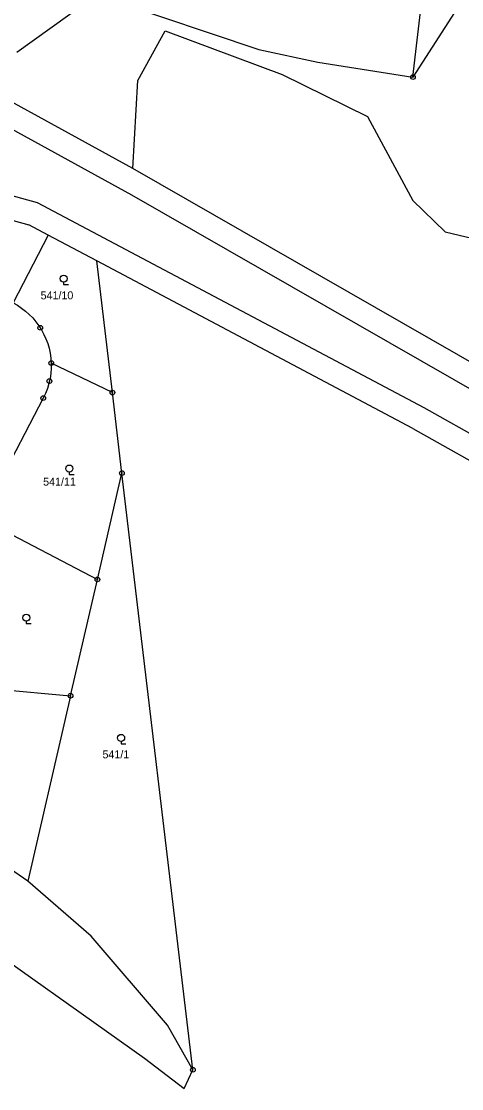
# Model space of a CAD drawing. Extents: x -759947 to -757003, y -1019641 to -1017100.
# Drawn here: x -757914.5 to -757821, y -1019278.9 to -1019052.2 of the extents above; entities that cross this region are included whole.
import ezdxf

# ---------------------------------------------------------------- set-up
doc = ezdxf.new("R2010")
doc.units = 0
doc.header["$LTSCALE"] = 0.68
for name, color, linetype, lineweight in [('1', 7, 'Continuous', 25), ('3', 7, 'Continuous', 25), ('8', 7, 'Continuous', 25)]:
    doc.layers.add(name, color=color, linetype=linetype, lineweight=lineweight)
doc.layers.add('2', color=7, linetype='Continuous')

msp = doc.modelspace()

# ---------------------------------------------------------------- linework, layer by layer
at = {"layer": '1'}
for p, q in [((-757831.29, -1019064.07), (-757827.47, -1019030.73)), ((-757813.04, -1019035.6), (-757831.29, -1019064.07)), ((-757895.26, -1019047.74), (-757864.04, -1019058.25)), ((-757963.05, -1019049.56), (-757891.09, -1019089.05)), ((-757915.46, -1019058.79), (-757900.92, -1019048.35)), ((-757890.77, -1019083.52), (-757947.21, -1019052.53)), ((-757889.7, -1019064.83), (-757883.96, -1019054.22)), ((-757883.96, -1019054.22), (-757859.04, -1019063.51)), ((-757864.04, -1019058.25), (-757851.51, -1019060.88)), ((-757851.51, -1019060.88), (-757831.29, -1019064.07)), ((-757859.04, -1019063.51), (-757840.93, -1019072.43)), ((-757890.77, -1019083.52), (-757889.7, -1019064.83)), ((-757840.93, -1019072.43), (-757831.31, -1019090.29)), ((-757810.34, -1019129.59), (-757890.77, -1019083.52)), ((-757911.01, -1019090.78), (-757918.97, -1019088.6)), ((-757828.94, -1019134.35), (-757911.01, -1019090.78)), ((-757891.09, -1019089.05), (-757812.79, -1019133.95)), ((-757831.31, -1019090.29), (-757824.44, -1019096.92)), ((-757920.78, -1019093.29), (-757912.86, -1019095.46)), ((-757908.76, -1019097.64), (-757912.86, -1019095.46)), ((-757908.76, -1019097.64), (-757916.23, -1019112.03)), ((-757898.47, -1019103.1), (-757908.76, -1019097.64)), ((-757824.44, -1019096.92), (-757776.68, -1019108.28)), ((-757831.34, -1019138.74), (-757898.47, -1019103.1)), ((-757895.14, -1019131.08), (-757898.47, -1019103.1)), ((-757895.14, -1019131.08), (-757908.12, -1019124.82)), ((-757893.11, -1019148.18), (-757895.14, -1019131.08)), ((-757909.82, -1019132.26), (-757923.16, -1019157.81)), ((-757763.77, -1019170.96), (-757828.94, -1019134.35)), ((-757831.34, -1019138.74), (-757766.17, -1019175.35)), ((-757898.33, -1019170.78), (-757893.11, -1019148.18)), ((-757878.03, -1019274.93), (-757893.11, -1019148.18)), ((-757923.16, -1019157.81), (-757898.33, -1019170.78)), ((-757904.03, -1019195.48), (-757898.33, -1019170.78)), ((-757931.34, -1019192.98), (-757904.03, -1019195.48)), ((-757904.03, -1019195.48), (-757913.12, -1019234.84)), ((-757913.12, -1019234.84), (-757931.26, -1019222.37)), ((-757899.66, -1019246.53), (-757913.12, -1019234.84)), ((-757883.42, -1019265.49), (-757899.66, -1019246.53)), ((-757878.03, -1019274.93), (-757883.42, -1019265.49)), ((-757888.29, -1019272.47), (-757879.92, -1019278.94)), ((-757879.92, -1019278.94), (-757878.03, -1019274.93))]:
    msp.add_line(p, q, dxfattribs=at)
for points in [[(-757916.23, -1019112.03), (-757915.31, -1019112.551), (-757914.429, -1019113.136), (-757913.591, -1019113.78), (-757912.8, -1019114.482), (-757912.06, -1019115.237), (-757911.375, -1019116.043), (-757910.748, -1019116.894), (-757910.181, -1019117.787), (-757909.679, -1019118.717), (-757909.243, -1019119.68), (-757908.875, -1019120.672), (-757908.578, -1019121.686), (-757908.352, -1019122.719), (-757908.199, -1019123.766), (-757908.12, -1019124.82)], [(-757908.12, -1019124.82), (-757908.13, -1019125.922), (-757908.219, -1019127.02), (-757908.386, -1019128.108), (-757908.632, -1019129.182), (-757908.954, -1019130.236), (-757909.35, -1019131.263), (-757909.82, -1019132.26)], [(-757936.99, -1019238.86), (-757928.26, -1019244.15), (-757888.29, -1019272.47)]]:
    msp.add_lwpolyline(points, dxfattribs=at)
at = {"layer": '3'}
for points in [[(-757905.49, -1019107.642), (-757905.49, -1019108.14), (-757904.489, -1019108.14)], [(-757904.29, -1019147.972), (-757904.29, -1019148.47), (-757903.289, -1019148.47)], [(-757913.42, -1019179.652), (-757913.42, -1019180.15), (-757912.419, -1019180.15)], [(-757893.28, -1019205.192), (-757893.28, -1019205.69), (-757892.279, -1019205.69)]]:
    msp.add_lwpolyline(points, dxfattribs=at)
for centre in [(-757905.4893, -1019106.8909), (-757904.2893, -1019147.2209), (-757913.4193, -1019178.9009), (-757893.2793, -1019204.4409)]:
    msp.add_circle(centre, 0.75, dxfattribs=at)
at = {"layer": '8'}
for centre, radius in [((-757831.29, -1019064.0699), 0.5), ((-757831.29, -1019064.0699), 0.0303), ((-757910.46, -1019117.3299), 0.5), ((-757910.46, -1019117.3299), 0.0303), ((-757908.12, -1019124.8199), 0.5), ((-757908.12, -1019124.8199), 0.0303), ((-757908.5, -1019128.6499), 0.5), ((-757908.5, -1019128.6499), 0.0303), ((-757909.82, -1019132.2599), 0.5), ((-757895.14, -1019131.0799), 0.5), ((-757895.14, -1019131.0799), 0.0303), ((-757909.82, -1019132.2599), 0.0303), ((-757893.11, -1019148.1799), 0.5), ((-757893.11, -1019148.1799), 0.0303), ((-757898.33, -1019170.7799), 0.5), ((-757898.33, -1019170.7799), 0.0303), ((-757904.03, -1019195.4799), 0.5), ((-757904.03, -1019195.4799), 0.0303), ((-757878.03, -1019274.9299), 0.5), ((-757878.03, -1019274.9299), 0.0303)]:
    msp.add_circle(centre, radius, dxfattribs=at)

# ---------------------------------------------------------------- texts
at = {"layer": '2'}
for s, p in [('541/10', (-757910.39, -1019111.285)), ('541/11', (-757909.85, -1019150.855)), ('541/1', (-757897.24, -1019208.775))]:
    msp.add_text(s, height=1.7, dxfattribs=at).set_placement(p)

doc.saveas('drawing.dxf')
